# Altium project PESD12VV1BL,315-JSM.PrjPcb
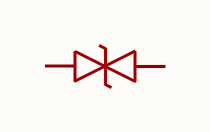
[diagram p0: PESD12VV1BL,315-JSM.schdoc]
1 sheet, 1 parts. Net scope: global (net labels, ports and power ports of the same name join across sheets).

## Sheet PESD12VV1BL,315-JSM.schdoc
size 127 x 101 mm

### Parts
D?  pesd12vv1bl,315-jsm  [DFN1006-2L-BI-1]  (value not drawn)

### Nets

Not connected (* = marked no-connect by the designer): D? 1 2

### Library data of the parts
D? = pesd12vv1bl,315-jsm: 极性:-;反向截止电压(Vrwm):12V;钳位电压:25V;峰值脉冲电流(Ipp):4A;峰值脉冲功率(Ppp):100W@8/20us;击穿电压(VBR):16V;; Manufacturer: JSMSEMI(杰盛微); AddInBom: yes; ModelId: 4f73e746f3be4d299816d29f03249d6e; ModelTransform: 40.1574,24.4094,0,0,0,0,0,0,0; Reverse Stand-Off Voltage (Vrwm): 12V; Clamping Voltage: 25V; Peak Pulse Current (Ipp): 4A; Voltage - Breakdown: 16V; Reverse Leakage Current (Ir): 1uA; level of protection: IEC 61000-4-2; Type: ESD; Junction Capacitance: 5pF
